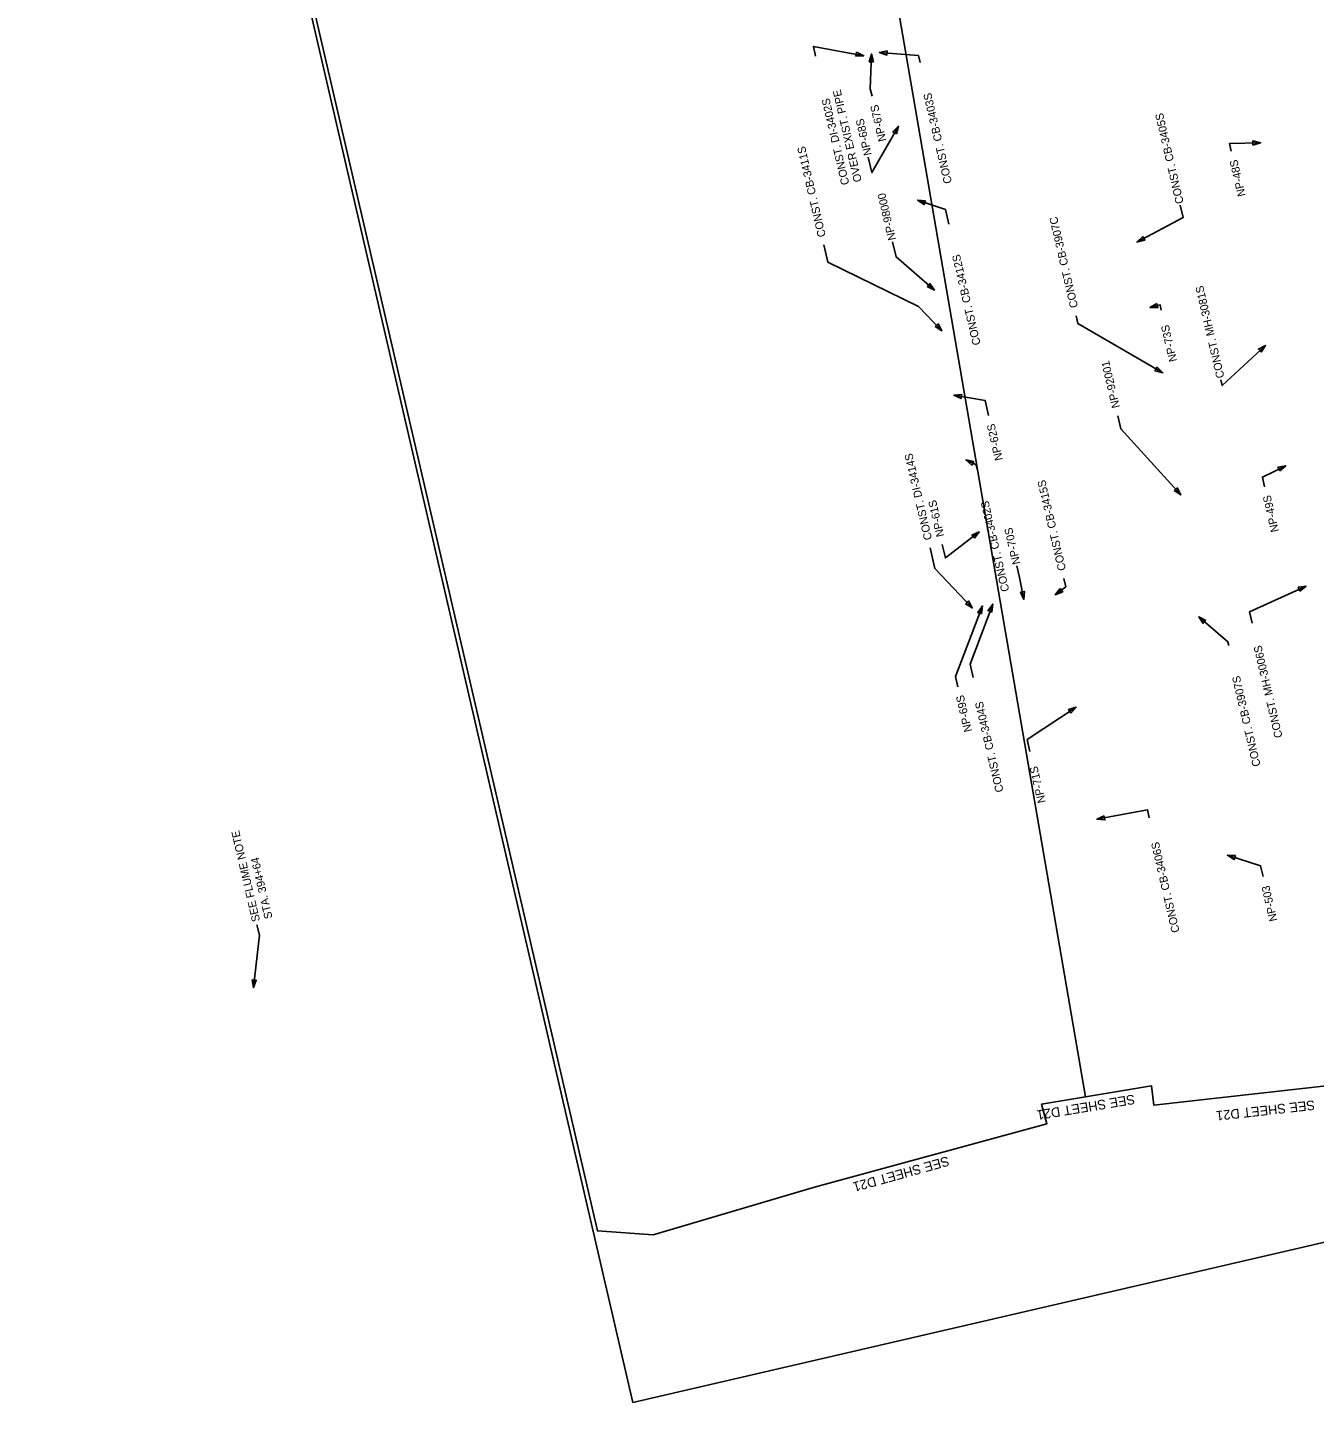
# Model space of a CAD drawing. Extents: x 1611522 to 1613146, y 1089913 to 1091760.
# Drawn here: x 1611608 to 1612412, y 1089913 to 1090772 of the extents above; entities that cross this region are included whole.
import ezdxf

# ---------------------------------------------------------------- set-up
doc = ezdxf.new("R2010")
doc.units = 0
for name, color, linetype in [('Level 2', 7, 'Continuous'), ('Plan_Clip', 7, 'Continuous'), ('RD_SHT_MatchLine', 7, 'Continuous'), ('RD_TX_Drainage', 7, 'Continuous')]:
    doc.layers.add(name, color=color, linetype=linetype)

msp = doc.modelspace()

# ---------------------------------------------------------------- linework, layer by layer
at = {"layer": 'Level 2'}
msp.add_lwpolyline([(1611985.8, 1089912.73), (1611607.62, 1091544.48), (1612539.42, 1091760.44), (1612917.6, 1090128.69)], close=True, dxfattribs=at)
at = {"layer": 'Plan_Clip'}
msp.add_lwpolyline([(1611661.84, 1091320.85), (1611963.63, 1090019.87), (1611998.55, 1090017.48), (1612099.34, 1090047.25), (1612244.44, 1090086.86), (1612241.08, 1090099.16), (1612241.08, 1090099.16), (1612309.86, 1090110.54), (1612311.21, 1090098.49), (1612443.02, 1090113.24), (1612450.72, 1090128.31), (1612534.46, 1090138.91), (1612564.39, 1090139.03), (1612734.94, 1090130.1), (1612765.21, 1090139.4), (1612877.73, 1090163.44), (1612841.1, 1090320.18), (1612867.45, 1090326.93), (1612548.32, 1091705.46)], dxfattribs=at)
msp.add_lwpolyline([(1611661.84, 1091320.85), (1611963.63, 1090019.87), (1611998.55, 1090017.48), (1612099.34, 1090047.25), (1612244.44, 1090086.86), (1612241.08, 1090099.16), (1612241.08, 1090099.16), (1612309.86, 1090110.54), (1612311.21, 1090098.49), (1612443.02, 1090113.24), (1612450.72, 1090128.31), (1612534.46, 1090138.91), (1612564.39, 1090139.03), (1612734.94, 1090130.1), (1612765.21, 1090139.4), (1612877.73, 1090163.44), (1612841.1, 1090320.18), (1612867.45, 1090326.93), (1612548.32, 1091705.46)], dxfattribs=at)
msp.add_lwpolyline([(1611661.84, 1091320.85), (1611963.63, 1090019.87), (1611998.55, 1090017.48), (1612099.34, 1090047.25), (1612244.44, 1090086.86), (1612241.08, 1090099.16), (1612241.08, 1090099.16), (1612309.86, 1090110.54), (1612311.21, 1090098.49), (1612443.02, 1090113.24), (1612450.72, 1090128.31), (1612534.46, 1090138.91), (1612564.39, 1090139.03), (1612734.94, 1090130.1), (1612765.21, 1090139.4), (1612877.73, 1090163.44), (1612841.1, 1090320.18), (1612867.45, 1090326.93), (1612548.32, 1091705.46)], dxfattribs=at)
msp.add_lwpolyline([(1611661.84, 1091320.85), (1611963.63, 1090019.87), (1611998.55, 1090017.48), (1612099.34, 1090047.25), (1612244.44, 1090086.86), (1612241.08, 1090099.16), (1612241.08, 1090099.16), (1612309.86, 1090110.54), (1612311.21, 1090098.49), (1612443.02, 1090113.24), (1612450.72, 1090128.31), (1612534.46, 1090138.91), (1612564.39, 1090139.03), (1612734.94, 1090130.1), (1612765.21, 1090139.4), (1612877.73, 1090163.44), (1612841.1, 1090320.18), (1612867.45, 1090326.93), (1612548.32, 1091705.46)], dxfattribs=at)
msp.add_lwpolyline([(1611661.84, 1091320.85), (1611963.63, 1090019.87), (1611998.55, 1090017.48), (1612099.34, 1090047.25), (1612244.44, 1090086.86), (1612241.08, 1090099.16), (1612241.08, 1090099.16), (1612309.86, 1090110.54), (1612311.21, 1090098.49), (1612443.02, 1090113.24), (1612450.72, 1090128.31), (1612534.46, 1090138.91), (1612564.39, 1090139.03), (1612734.94, 1090130.1), (1612765.21, 1090139.4), (1612877.73, 1090163.44), (1612841.1, 1090320.18), (1612867.45, 1090326.93), (1612548.32, 1091705.46)], dxfattribs=at)
msp.add_lwpolyline([(1611661.84, 1091320.85), (1611963.63, 1090019.87), (1611998.55, 1090017.48), (1612099.34, 1090047.25), (1612244.44, 1090086.86), (1612241.08, 1090099.16), (1612241.08, 1090099.16), (1612309.86, 1090110.54), (1612311.21, 1090098.49), (1612443.02, 1090113.24), (1612450.72, 1090128.31), (1612534.46, 1090138.91), (1612564.39, 1090139.03), (1612734.94, 1090130.1), (1612765.21, 1090139.4), (1612877.73, 1090163.44), (1612841.1, 1090320.18), (1612867.45, 1090326.93), (1612548.32, 1091705.46)], dxfattribs=at)
msp.add_lwpolyline([(1611661.84, 1091320.85), (1611963.63, 1090019.87), (1611998.55, 1090017.48), (1612099.34, 1090047.25), (1612244.44, 1090086.86), (1612241.08, 1090099.16), (1612241.08, 1090099.16), (1612309.86, 1090110.54), (1612311.21, 1090098.49), (1612443.02, 1090113.24), (1612450.72, 1090128.31), (1612534.46, 1090138.91), (1612564.39, 1090139.03), (1612734.94, 1090130.1), (1612765.21, 1090139.4), (1612877.73, 1090163.44), (1612841.1, 1090320.18), (1612867.45, 1090326.93), (1612548.32, 1091705.46)], dxfattribs=at)
msp.add_lwpolyline([(1611963.63, 1090019.87), (1611998.55, 1090017.48), (1612099.34, 1090047.25), (1612244.44, 1090086.86), (1612241.08, 1090099.16), (1612268.58, 1090103.71), (1612018.61, 1091555.02), (1611981.67, 1091541.05), (1611980.37, 1091551.71), (1611930.48, 1091534.68), (1611926.18, 1091544.55), (1611855.59, 1091525.38), (1611674.63, 1091416.97), (1611695.52, 1091328.83), (1611661.84, 1091320.85)], close=True, dxfattribs=at)
at = {"layer": 'RD_TX_Drainage'}
for points in [[(1612099.97, 1090753.64), (1612098.55, 1090759.77), (1612130.02, 1090753.95)], [(1612135.18, 1090728.57), (1612134.11, 1090733.18), (1612134.93, 1090754.96)], [(1612165.18, 1090749.68), (1612164.17, 1090754.05), (1612139.83, 1090756)], [(1612132.87, 1090690.67), (1612135.12, 1090680.95), (1612151.81, 1090709.89)], [(1612359.64, 1090694.24), (1612358.5, 1090699.13), (1612377.91, 1090699.54)], [(1612183.14, 1090648.76), (1612181.05, 1090657.78), (1612163.66, 1090663.74)], [(1612327.75, 1090660.52), (1612329.53, 1090652.8), (1612300.69, 1090637.58)], [(1612105.07, 1090635.84), (1612107.56, 1090625.08), (1612164.15, 1090597.35), (1612178.82, 1090582.14)], [(1612148.01, 1090637.68), (1612150.2, 1090628.24), (1612174.11, 1090607.52)], [(1612315.9, 1090594.93), (1612315.11, 1090598.34), (1612308.76, 1090596.71)], [(1612262.62, 1090591.57), (1612263.77, 1090586.6), (1612316.76, 1090555.82)], [(1612353.14, 1090551.57), (1612353.99, 1090547.93), (1612380.93, 1090573.03)], [(1612207.99, 1090529.29), (1612205.83, 1090538.6), (1612186.32, 1090541.83)], [(1612288.72, 1090529.03), (1612290.61, 1090520.87), (1612328.07, 1090479.63)], [(1612201.02, 1090494.82), (1612200.18, 1090498.42), (1612193.81, 1090501.52)], [(1612380.41, 1090484.65), (1612379.01, 1090490.7), (1612393.61, 1090497.87)], [(1612179.07, 1090448.57), (1612180.99, 1090440.26), (1612202.18, 1090456.47)], [(1612171.45, 1090446.6), (1612174.46, 1090433.59), (1612197.77, 1090409.06)], [(1612225.68, 1090435.25), (1612227.37, 1090427.97), (1612230.09, 1090414.36)], [(1612255.11, 1090427.46), (1612256.31, 1090422.29), (1612249.67, 1090417.21)], [(1612372.66, 1090399.57), (1612371.03, 1090406.6), (1612406.33, 1090422.71)], [(1612188.71, 1090359.78), (1612187.24, 1090366.1), (1612204.16, 1090410.23)], [(1612198.34, 1090365.62), (1612196.42, 1090373.9), (1612210.55, 1090411.41)], [(1612358.03, 1090385.58), (1612357.48, 1090387.94), (1612339.29, 1090403.42)], [(1612233.82, 1090319.29), (1612232.09, 1090326.77), (1612262.68, 1090347.11)], [(1612308.33, 1090277.93), (1612307.18, 1090282.93), (1612275.71, 1090277.02)], [(1612379.49, 1090241.26), (1612377.92, 1090248.03), (1612357.24, 1090254.56)], [(1611750.95, 1090211.12), (1611752.47, 1090204.58), (1611748.71, 1090171.84)]]:
    msp.add_lwpolyline(points, dxfattribs=at)
for points in [[(1612125.04, 1090753.56), (1612130.02, 1090753.95), (1612125.51, 1090756.1)], [(1612136.04, 1090750.09), (1612134.93, 1090754.96), (1612133.45, 1090750.19)], [(1612144.74, 1090756.9), (1612139.83, 1090756), (1612144.54, 1090754.32)], [(1612150.52, 1090705.06), (1612151.81, 1090709.89), (1612148.28, 1090706.35)], [(1612373.11, 1090698.15), (1612377.91, 1090699.54), (1612373.06, 1090700.73)], [(1612168.65, 1090663.4), (1612163.66, 1090663.74), (1612167.81, 1090660.95)], [(1612304.36, 1090640.98), (1612300.69, 1090637.58), (1612305.57, 1090638.69)], [(1612169.61, 1090609.71), (1612174.11, 1090607.52), (1612171.3, 1090611.66)], [(1612313.11, 1090599.17), (1612308.76, 1090596.71), (1612313.76, 1090596.66)], [(1612174.54, 1090584.72), (1612178.82, 1090582.14), (1612176.4, 1090586.51)], [(1612378.28, 1090568.79), (1612380.93, 1090573.03), (1612376.51, 1090570.69)], [(1612311.93, 1090557.13), (1612316.76, 1090555.82), (1612313.23, 1090559.37)], [(1612191.29, 1090542.32), (1612186.32, 1090541.83), (1612190.87, 1090539.76)], [(1612198.72, 1090500.57), (1612193.81, 1090501.52), (1612197.58, 1090498.24)], [(1612389.85, 1090494.58), (1612393.61, 1090497.87), (1612388.71, 1090496.9)], [(1612323.87, 1090482.33), (1612328.07, 1090479.63), (1612325.78, 1090484.07)], [(1612199.13, 1090452.5), (1612202.18, 1090456.47), (1612197.56, 1090454.56)], [(1612227.88, 1090418.84), (1612230.09, 1090414.36), (1612230.42, 1090419.35)], [(1612252.72, 1090421.17), (1612249.67, 1090417.21), (1612254.29, 1090419.12)], [(1612402.47, 1090419.53), (1612406.33, 1090422.71), (1612401.4, 1090421.89)], [(1612193.5, 1090411.67), (1612197.77, 1090409.06), (1612195.38, 1090413.45)], [(1612203.64, 1090405.26), (1612204.16, 1090410.23), (1612201.22, 1090406.19)], [(1612210.06, 1090406.44), (1612210.55, 1090411.41), (1612207.64, 1090407.35)], [(1612343.81, 1090401.27), (1612339.29, 1090403.42), (1612342.13, 1090399.3)], [(1612259.38, 1090343.36), (1612262.68, 1090347.11), (1612257.95, 1090345.52)], [(1612280.22, 1090279.18), (1612275.71, 1090277.02), (1612280.7, 1090276.64)], [(1612362.24, 1090254.34), (1612357.24, 1090254.56), (1612361.46, 1090251.87)], [(1611747.97, 1090176.79), (1611748.71, 1090171.84), (1611750.54, 1090176.49)]]:
    msp.add_lwpolyline(points, close=True, dxfattribs=at)

# ---------------------------------------------------------------- texts
at = {"layer": 'RD_SHT_MatchLine'}
for rotation, p in [(189.39203, (1612298.85, 1090105.17)), (186.3858, (1612411.49, 1090101.56)), (195.5667, (1612182.45, 1090066.64))]:
    msp.add_text('SEE SHEET D21', height=6, rotation=rotation, dxfattribs=at).set_placement(p)
at = {"layer": 'RD_TX_Drainage'}
for s, p in [('CONST. DI-3402S', (1612121.03, 1090673.82)), ('OVER EXIST. PIPE', (1612128.83, 1090675.63)), ('CONST. CB-3403S', (1612185.14, 1090674.65)), ('NP-67S', (1612144.15, 1090700.93)), ('CONST. CB-3405S', (1612329.95, 1090662.06)), ('NP-68S', (1612135.08, 1090692.21)), ('CONST. CB-3411S', (1612106.37, 1090641.27)), ('NP-48S', (1612368.61, 1090666.6)), ('NP-98000', (1612150.22, 1090639.22)), ('CONST. CB-3907C', (1612263.93, 1090597.01)), ('CONST. CB-3412S', (1612203.09, 1090573.73)), ('CONST. MH-3081S', (1612355.35, 1090553.11)), ('NP-73S', (1612325.78, 1090563.39)), ('NP-92001', (1612290.03, 1090534.47)), ('NP-62S', (1612216.96, 1090501.65)), ('CONST. DI-3414S', (1612172.75, 1090452.03)), ('CONST. CB-3415S', (1612256.42, 1090432.89)), ('NP-49S', (1612389.39, 1090457)), ('NP-61S', (1612180.37, 1090454.01)), ('CONST. CB-3402S', (1612220.97, 1090419.79)), ('NP-70S', (1612227.89, 1090436.79)), ('CONST. MH-3006S', (1612391.71, 1090328.44)), ('CONST. CB-3907S', (1612377.98, 1090310.55)), ('NP-69S', (1612197.68, 1090332.14)), ('CONST. CB-3404S', (1612217.39, 1090294.48)), ('NP-71S', (1612243.7, 1090287.75)), ('SEE FLUME NOTE', (1611752.94, 1090213.63)), ('CONST. CB-3406S', (1612327.39, 1090206.8)), ('STA. 394+64', (1611760.73, 1090215.44)), ('NP-503', (1612388.41, 1090213.85))]:
    msp.add_text(s, height=5, rotation=103.04878, dxfattribs=at).set_placement(p)

doc.saveas('drawing.dxf')
